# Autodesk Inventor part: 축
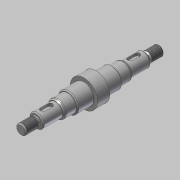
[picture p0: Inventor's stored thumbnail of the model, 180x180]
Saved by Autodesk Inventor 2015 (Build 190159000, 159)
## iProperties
Created: 2019-09
Part Number: 축
Material: 강철, 연강
Document SubType Name: Modeling
Designer: mduedu
Density: 7.86 g/cm^3
Mass: 210.278 g
Surface Area: 69.4769 cm^2
Volume: 26.7529 cm^3
Appearance: 강철
Author: mduedu
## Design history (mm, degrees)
sketch "스케치1"
  geometry: L1 (0, 0)-(15, 0); L2 (15, 0)-(15, 5); L3 (15, 5)-(0, 5); L4 (0, 5)-(0, 0); L5 (15, 0)-(34, 0); L6 (34, 0)-(34, 7); L7 (34, 7)-(15, 7); L8 (15, 7)-(15, 0); L9 (34, 0)-(46, 0); L10 (46, 0)-(46, 8.5); L11 (46, 8.5)-(34, 8.5); L12 (34, 8.5)-(34, 0); L13 (46, 0)-(62, 0); L14 (62, 10)-(46, 10); L15 (46, 10)-(46, 0); L16 (62, 10)-(62, 0); L17 (62, 0)-(68, 0); L18 (68, 0)-(68, 13.5); L19 (68, 13.5)-(62, 13.5); L20 (62, 13.5)-(62, 0)
  constraints: 40 end point, 10 parallel, 5 horizontal, 4 perpendicular, 1 vertical
  dimensions: "d2" = 15 distance of L2.end L3.end; "d3" = 19 distance of L6.end L7.end; "d8" = 16 distance of L14.start L14.end; "d9" = 10 diameter of L3 L1; "d10" = 14 diameter of L7 L5; "d11" = 17 diameter of L11 L9; "d12" = 20 diameter of L14 L13; "d73" = 12 distance of L10.end L11.end (derived); "d74" = 27 diameter of L19 L17; "d75" = 6 distance of L18.end L19.end; "d76" = 68 distance between parallel lines of L4 L18
revolve "회전1" sketch "스케치1" stored, may be unused: angle "d17" = 90 deg
revolve "회전2" stored, may be unused: angle "d22" = 90 deg
fillet "모깎기1" dims "d23" = 0.6
feature "스레드1" dims "d24" = 10, "d25" = 0
chamfer "모따기1" distance "d26" = 1; stored, may be unused: second distance "d27" = 2, angle "d28" = 45 deg
chamfer "모따기2" distance "d29" = 1; stored, may be unused: second distance "d30" = 2, angle "d31" = 45 deg
chamfer "모따기3" distance "d32" = 1.819; stored, may be unused: second distance "d33" = 2, angle "d34" = 30 deg
fillet "모깎기2" dims "d35" = 2
chamfer "모따기4" distance "d36" = 1; stored, may be unused: second distance "d37" = 2, angle "d38" = 30 deg
fillet "모깎기3" dims "d39" = 0.3
node "작업 평면1"
sketch "스케치3" dims "d51" = 12
  geometry: L1 (3, -2.5)-(-4, -2.5); L2 (-4, -2.5)-(-4, 2.5); L3 (-4, 2.5)-(3, 2.5); L4 (3, 2.5)-(3, -2.5); L5 (-9.5, 7.45)-(-9.5, -7.45) reference; 3 further points
  constraints: 8 end point, 2 midpoint, 2 parallel, 2 vertical alignment, 1 horizontal, 1 horizontal alignment, 1 perpendicular, 4 other
  dimensions: "d50" = 3 dimension on L5; "d52" = 5 distance between parallel lines of L3 L1
extrude "돌출1" cut sketch "스케치3" distance "d53" = 3; taper "d54" = 0 deg
node "솔리드1"
mirror "대칭1"
sketch "스케치2"
  geometry: L1 (0, -5)-(0, 5) reference; L2 (0, 5)-(15, 5) reference; L3 (15, 5)-(15, 7) reference; L4 (15, 7)-(34, 7) reference; L5 (34, 7)-(34, 8.5) reference; L6 (34, 8.5)-(46, 8.5) reference; L7 (46, 8.5)-(46, 10) reference; L8 (46, 10)-(62, 10) reference; L9 (62, -10)-(46, -10) reference; L10 (46, -10)-(46, -8.5) reference; L11 (46, -8.5)-(34, -8.5) reference; L12 (34, -8.5)-(34, -7) reference; L13 (34, -7)-(15, -7) reference; L14 (15, -7)-(15, -5) reference; L15 (15, -5)-(0, -5) reference; L16 (0, 0)-(74, 0); L17 (15, 5)-(12.014, 5); L18 (13.4, 4.2)-(15, 4.2); L19 (15, 4.2)-(15, 5); L20 (12.014, 5)-(13.4, 4.2); L21 (62, 10)-(62, 13.5) reference; L22 (62, 13.5)-(68, 13.5) reference; L23 (68, 13.5)-(68, -13.5) reference; L24 (68, -13.5)-(62, -13.5) reference; L25 (62, -13.5)-(62, -10) reference
  constraints: 10 end point, 1 horizontal, 1 parallel, 1 vertical
  dimensions: "d18" = 30 deg angle of L2 L20; "d19" = 8.4 diameter of L18 L16; "d21" = 2.986 distance from line of L17.end L19
node "절단 모서리 투영1"
